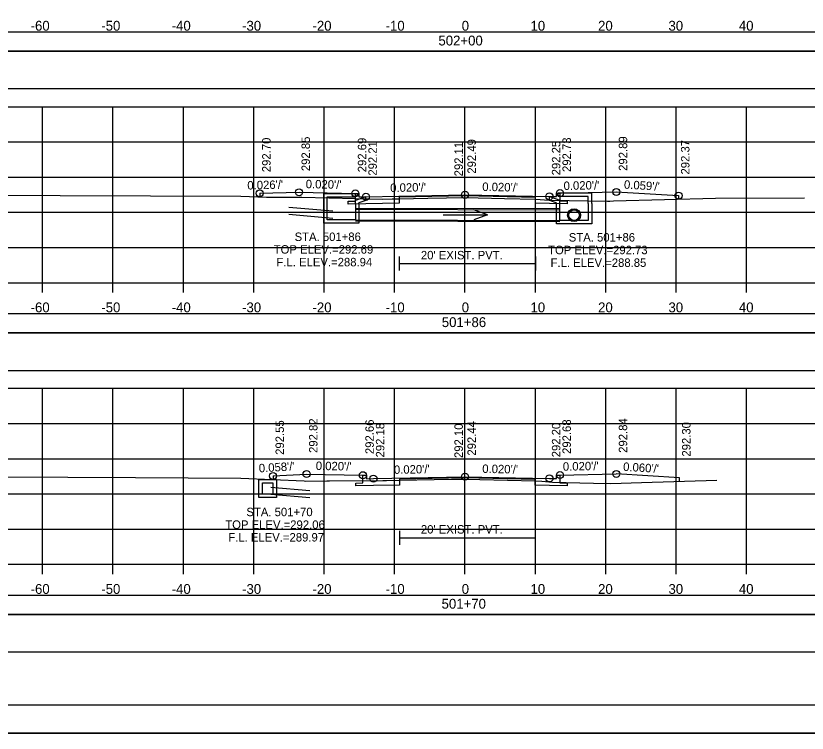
# Model space of a CAD drawing. Extents: x 1370538 to 1372872, y 376220 to 381127.
# Drawn here: x 1372644.8 to 1372757.3, y 376647.1 to 376749 of the extents above; entities that cross this region are included whole.
import ezdxf

# ---------------------------------------------------------------- set-up
doc = ezdxf.new("R2010")
doc.units = 0
for name, color, linetype in [('R_Border', 7, 'Continuous'), ('R_Border Notes', 7, 'Continuous'), ('R_Border PE', 7, 'Continuous'), ('R_Border Prem', 7, 'Continuous'), ('R_Dimension', 7, 'Continuous'), ('R_Fin Surface', 7, 'Continuous'), ('R_Grid', 7, 'Continuous'), ('R_No Plot', 7, 'Continuous'), ('R_Water', 7, 'Continuous'), ('R_Water Annot', 7, 'Continuous'), ('R_Xsect Elev', 7, 'Continuous'), ('R_Xsect Slope', 7, 'Continuous'), ('T_Detection Zones', 7, 'Continuous')]:
    doc.layers.add(name, color=color, linetype=linetype)

msp = doc.modelspace()

# ---------------------------------------------------------------- linework, layer by layer
at = {"layer": 'R_Border'}
for p, q in [((1372699.29, 376714.81), (1372699.29, 376712.81)), ((1372699.29, 376713.81), (1372718.69, 376713.81)), ((1372718.69, 376714.81), (1372718.69, 376712.81)), ((1372699.34, 376675.86), (1372699.34, 376673.86)), ((1372718.62, 376675.86), (1372718.62, 376673.86)), ((1372699.34, 376674.86), (1372718.62, 376674.86))]:
    msp.add_line(p, q, dxfattribs=at)
for points in [[(1372722.15, 376723.82), (1372722.15, 376722.73), (1372723.15, 376722.71), (1372723.15, 376722.29), (1372720.65, 376722.34), (1372718.69, 376722.38), (1372718.69, 376723.21), (1372708.65, 376723.41), (1372699.29, 376723.22), (1372699.29, 376722.39), (1372694.58, 376722.3), (1372692.08, 376722.25), (1372692.08, 376722.66), (1372693.08, 376722.68), (1372693.08, 376723.78)], [(1372722.15, 376683.77), (1372722.15, 376682.68), (1372723.15, 376682.66), (1372723.15, 376682.24), (1372720.65, 376682.29), (1372718.63, 376682.33), (1372718.62, 376683.16), (1372708.65, 376683.36), (1372699.34, 376683.18), (1372699.34, 376682.34), (1372695.65, 376682.27), (1372693.15, 376682.22), (1372693.15, 376682.64), (1372694.15, 376682.66), (1372694.15, 376683.75)]]:
    msp.add_lwpolyline(points, dxfattribs=at)
at = {"layer": 'R_Border Notes'}
msp.add_line((1372866.83, 376651.09), (1372550.65, 376651.09), dxfattribs=at)
at = {"layer": 'R_Border Prem'}
for p, q in [((1372558.65, 376711.09), (1372858.65, 376711.09)), ((1372648.65, 376709.69), (1372648.65, 376711.09)), ((1372658.65, 376709.69), (1372658.65, 376711.09)), ((1372668.65, 376709.69), (1372668.65, 376711.09)), ((1372678.65, 376709.69), (1372678.65, 376711.09)), ((1372688.65, 376709.69), (1372688.65, 376711.09)), ((1372698.65, 376709.69), (1372698.65, 376711.09)), ((1372708.65, 376709.69), (1372708.65, 376711.09)), ((1372718.65, 376709.69), (1372718.65, 376711.09)), ((1372728.65, 376709.69), (1372728.65, 376711.09)), ((1372738.65, 376709.69), (1372738.65, 376711.09)), ((1372748.65, 376709.69), (1372748.65, 376711.09)), ((1372558.65, 376671.09), (1372858.65, 376671.09)), ((1372648.65, 376669.69), (1372648.65, 376671.09)), ((1372658.65, 376669.69), (1372658.65, 376671.09)), ((1372668.65, 376669.69), (1372668.65, 376671.09)), ((1372678.65, 376669.69), (1372678.65, 376671.09)), ((1372688.65, 376669.69), (1372688.65, 376671.09)), ((1372698.65, 376669.69), (1372698.65, 376671.09)), ((1372708.65, 376669.69), (1372708.65, 376671.09)), ((1372718.65, 376669.69), (1372718.65, 376671.09)), ((1372728.65, 376669.69), (1372728.65, 376671.09)), ((1372738.65, 376669.69), (1372738.65, 376671.09)), ((1372748.65, 376669.69), (1372748.65, 376671.09))]:
    msp.add_line(p, q, dxfattribs=at)
at = {"layer": 'R_Dimension'}
for points in [[(1372586.95, 376723.74), (1372676.82, 376723.4), (1372680.47, 376723.25), (1372681.64, 376723.25), (1372685.5, 376723.24), (1372697, 376722.95), (1372698.31, 376722.99), (1372699.29, 376723.02), (1372703.39, 376723.11), (1372708.67, 376723.2), (1372714.27, 376723.07), (1372718.69, 376722.97), (1372720.61, 376722.81), (1372720.74, 376722.8), (1372728.92, 376722.69), (1372729.21, 376722.68), (1372729.74, 376722.7), (1372744.25, 376723.11), (1372756.89, 376723.13)], [(1372558.65, 376683.74), (1372562.8, 376683.64), (1372568.21, 376683.67), (1372584.9, 376683.81), (1372661.87, 376683.41), (1372676.81, 376683.33), (1372685.83, 376682.93), (1372686.06, 376682.92), (1372689.02, 376682.96), (1372689.17, 376682.96), (1372689.39, 376682.96), (1372697, 376682.98), (1372697.51, 376682.99), (1372699.34, 376683.05), (1372706.72, 376683.17), (1372708.67, 376683.19), (1372710.75, 376683.14), (1372718.62, 376682.96), (1372719.59, 376682.88), (1372721.07, 376682.75), (1372726.93, 376682.63), (1372729.37, 376682.58), (1372733.74, 376682.72), (1372744.41, 376683.06)]]:
    msp.add_lwpolyline(points, dxfattribs=at)
at = {"layer": 'R_Fin Surface'}
for p, q in [((1372679.49, 376723.79), (1372679.49, 376723.29)), ((1372738.99, 376723.46), (1372738.99, 376722.96)), ((1372681.39, 376683.64), (1372681.39, 376683.13))]:
    msp.add_line(p, q, dxfattribs=at)
for points in [[(1372679.49, 376723.79), (1372685.08, 376723.94), (1372693.08, 376723.78), (1372693.58, 376723.78), (1372693.58, 376723.28), (1372694.58, 376723.3), (1372708.65, 376723.58), (1372720.65, 376723.34), (1372721.65, 376723.32), (1372721.65, 376723.82), (1372722.15, 376723.82), (1372730.15, 376723.98), (1372738.99, 376723.46)], [(1372681.39, 376683.64), (1372686.15, 376683.91), (1372694.15, 376683.75), (1372694.65, 376683.75), (1372694.65, 376683.25), (1372695.65, 376683.27), (1372708.65, 376683.53), (1372720.65, 376683.29), (1372721.65, 376683.27), (1372721.65, 376683.77), (1372722.15, 376683.77), (1372730.15, 376683.93)], [(1372739.14, 376682.89), (1372739.14, 376683.39), (1372730.15, 376683.93)]]:
    msp.add_lwpolyline(points, dxfattribs=at)
at = {"layer": 'R_Grid'}
for p, q in [((1372558.65, 376736.09), (1372858.65, 376736.09)), ((1372648.65, 376711.09), (1372648.65, 376736.09)), ((1372658.65, 376711.09), (1372658.65, 376736.09)), ((1372668.65, 376711.09), (1372668.65, 376736.09)), ((1372678.65, 376711.09), (1372678.65, 376736.09)), ((1372688.65, 376711.09), (1372688.65, 376736.09)), ((1372698.65, 376711.09), (1372698.65, 376736.09)), ((1372708.65, 376711.09), (1372708.65, 376736.09)), ((1372718.65, 376711.09), (1372718.65, 376736.09)), ((1372728.65, 376711.09), (1372728.65, 376736.09)), ((1372738.65, 376711.09), (1372738.65, 376736.09)), ((1372748.65, 376711.09), (1372748.65, 376736.09)), ((1372558.65, 376731.09), (1372858.65, 376731.09)), ((1372558.65, 376726.09), (1372858.65, 376726.09)), ((1372558.65, 376721.09), (1372858.65, 376721.09)), ((1372558.65, 376716.09), (1372858.65, 376716.09)), ((1372558.65, 376711.09), (1372858.65, 376711.09)), ((1372558.65, 376696.09), (1372858.65, 376696.09)), ((1372648.65, 376671.09), (1372648.65, 376696.09)), ((1372658.65, 376671.09), (1372658.65, 376696.09)), ((1372668.65, 376671.09), (1372668.65, 376696.09)), ((1372678.65, 376671.09), (1372678.65, 376696.09)), ((1372688.65, 376671.09), (1372688.65, 376696.09)), ((1372698.65, 376671.09), (1372698.65, 376696.09)), ((1372708.65, 376671.09), (1372708.65, 376696.09)), ((1372718.65, 376671.09), (1372718.65, 376696.09)), ((1372728.65, 376671.09), (1372728.65, 376696.09)), ((1372738.65, 376671.09), (1372738.65, 376696.09)), ((1372748.65, 376671.09), (1372748.65, 376696.09)), ((1372558.65, 376691.09), (1372858.65, 376691.09)), ((1372558.65, 376686.09), (1372858.65, 376686.09)), ((1372558.65, 376681.09), (1372858.65, 376681.09)), ((1372558.65, 376676.09), (1372858.65, 376676.09)), ((1372558.65, 376671.09), (1372858.65, 376671.09))]:
    msp.add_line(p, q, dxfattribs=at)
at = {"layer": 'R_No Plot'}
for p, q in [((1372683.61, 376721.84), (1372689.88, 376721.29)), ((1372693.08, 376721.7), (1372722.15, 376721.61)), ((1372683.61, 376720.83), (1372689.88, 376720.27)), ((1372693.08, 376719.86), (1372722.15, 376719.78)), ((1372681.07, 376682.07), (1372686.59, 376681.58)), ((1372681.07, 376681.05), (1372686.59, 376680.57)), ((1372538.25, 376647.11), (1372871.58, 376647.11))]:
    msp.add_line(p, q, dxfattribs=at)
for points in [[(1372538.24, 376860.44), (1372871.58, 376860.44), (1372871.58, 376647.11), (1372538.24, 376647.11)], [(1372784.57, 376856.55), (1372784.57, 376846.67), (1372820.3, 376846.67), (1372820.3, 376843.75), (1372843.5, 376843.75), (1372843.5, 376819.42), (1372866.83, 376819.42), (1372866.83, 376651.09), (1372550.65, 376651.09), (1372550.65, 376856.55)]]:
    msp.add_lwpolyline(points, close=True, dxfattribs=at)
for centre, radius in [((1372679.49, 376723.79), 0.5), ((1372685.08, 376723.94), 0.5), ((1372693.08, 376723.78), 0.5), ((1372708.65, 376723.58), 0.5), ((1372722.15, 376723.82), 0.5), ((1372730.15, 376723.98), 0.5), ((1372738.99, 376723.46), 0.5), ((1372694.58, 376723.3), 0.5), ((1372720.65, 376723.34), 0.5), ((1372724.15, 376720.69), 0.917), ((1372681.39, 376683.64), 0.5), ((1372686.15, 376683.91), 0.5), ((1372694.15, 376683.75), 0.5), ((1372695.65, 376683.27), 0.5), ((1372708.65, 376683.53), 0.5), ((1372720.65, 376683.29), 0.5), ((1372722.15, 376683.77), 0.5), ((1372730.15, 376683.93), 0.5)]:
    msp.add_circle(centre, radius, dxfattribs=at)
at = {"layer": 'R_Water'}
for p, q in [((1372688.58, 376723.78), (1372693.33, 376723.78)), ((1372688.58, 376722.28), (1372688.58, 376723.78)), ((1372689.08, 376722.28), (1372689.08, 376723.28)), ((1372689.08, 376723.28), (1372693.08, 376723.28)), ((1372693.41, 376723.61), (1372693.08, 376723.28)), ((1372694.58, 376723.3), (1372693.08, 376722.78)), ((1372693.41, 376723.61), (1372693.33, 376723.78)), ((1372720.65, 376723.34), (1372722.15, 376722.82)), ((1372720.65, 376722.81), (1372721.65, 376722.46)), ((1372721.81, 376723.65), (1372721.9, 376723.82)), ((1372721.81, 376723.65), (1372722.15, 376723.32)), ((1372726.65, 376723.82), (1372721.9, 376723.82)), ((1372726.15, 376723.32), (1372722.15, 376723.32)), ((1372722.15, 376722.32), (1372722.15, 376722.82)), ((1372726.15, 376722.32), (1372726.15, 376723.32)), ((1372726.65, 376722.32), (1372726.65, 376723.82)), ((1372683.61, 376721.84), (1372689.88, 376721.28)), ((1372693.08, 376722.28), (1372693.08, 376722.78)), ((1372694.58, 376722.77), (1372693.58, 376722.42)), ((1372693.58, 376722.28), (1372693.58, 376722.42)), ((1372721.65, 376722.32), (1372721.65, 376722.46)), ((1372683.61, 376720.84), (1372689.88, 376720.28)), ((1372693.08, 376721.53), (1372722.15, 376721.44)), ((1372693.08, 376720.03), (1372722.15, 376719.94)), ((1372681.07, 376682.06), (1372686.59, 376681.57)), ((1372681.07, 376681.06), (1372686.59, 376680.57))]:
    msp.add_line(p, q, dxfattribs=at)
for points in [[(1372694.58, 376722.77), (1372694.58, 376723.3)], [(1372720.65, 376722.81), (1372720.65, 376723.34)], [(1372693.58, 376722.28), (1372693.58, 376719.53), (1372691.08, 376719.53), (1372688.58, 376719.53), (1372688.58, 376722.28)], [(1372693.08, 376722.28), (1372693.08, 376720.03), (1372691.08, 376720.03), (1372689.08, 376720.03), (1372689.08, 376722.28)], [(1372726.65, 376722.32), (1372726.65, 376719.44), (1372724.15, 376719.44), (1372721.65, 376719.44), (1372721.65, 376722.32)], [(1372726.15, 376722.32), (1372726.15, 376719.94), (1372724.15, 376719.94), (1372722.15, 376719.94), (1372722.15, 376722.32)]]:
    msp.add_lwpolyline(points, dxfattribs=at)
for points in [[(1372680.62, 376683.15), (1372681.87, 376683.15), (1372681.87, 376680.56), (1372680.62, 376680.56), (1372679.37, 376680.56), (1372679.37, 376683.15)], [(1372680.62, 376682.65), (1372681.37, 376682.65), (1372681.37, 376681.06), (1372680.62, 376681.06), (1372679.87, 376681.06), (1372679.87, 376682.65)]]:
    msp.add_lwpolyline(points, close=True, dxfattribs=at)
msp.add_circle((1372724.15, 376720.69), 0.75, dxfattribs=at)
at = {"layer": 'R_Water Annot'}
for p, q in [((1372705.55, 376720.75), (1372711.83, 376720.73)), ((1372711.83, 376720.73), (1372709.91, 376721.43)), ((1372711.83, 376720.73), (1372709.91, 376720.03))]:
    msp.add_line(p, q, dxfattribs=at)
at = {"layer": 'R_Xsect Elev'}
for p, q in [((1372708.65, 376723.2), (1372708.65, 376733.2)), ((1372708.65, 376683.19), (1372708.65, 376693.19))]:
    msp.add_line(p, q, dxfattribs=at)
at = {"layer": 'T_Detection Zones'}
for points in [[(1372552.66, 376743.99), (1372864.63, 376743.99), (1372864.63, 376746.69), (1372552.66, 376746.69)], [(1372552.66, 376738.66), (1372864.63, 376738.66), (1372864.63, 376743.99), (1372552.66, 376743.99)], [(1372552.66, 376703.96), (1372864.63, 376703.96), (1372864.63, 376706.67), (1372552.66, 376706.67)], [(1372552.66, 376698.64), (1372864.63, 376698.64), (1372864.63, 376703.96), (1372552.66, 376703.96)], [(1372552.66, 376663.98), (1372864.63, 376663.98), (1372864.63, 376666.68), (1372552.66, 376666.68)], [(1372552.66, 376658.66), (1372864.63, 376658.66), (1372864.63, 376663.98), (1372552.66, 376663.98)]]:
    msp.add_lwpolyline(points, close=True, dxfattribs=at)

# ---------------------------------------------------------------- texts
at = {"layer": 'R_Border PE'}
for s, p in [('-60', (1372646.95, 376746.89)), ('-50', (1372656.99, 376746.89)), ('-40', (1372666.99, 376746.89)), ('-30', (1372676.99, 376746.89)), ('-20', (1372686.99, 376746.89)), ('-10', (1372697.38, 376746.89)), ('0', (1372708.19, 376746.89)), ('10', (1372717.96, 376746.89)), ('20', (1372727.56, 376746.89)), ('30', (1372737.56, 376746.89)), ('40', (1372747.56, 376746.89)), ('502+00', (1372704.88, 376744.79)), ('-60', (1372646.95, 376706.89)), ('-50', (1372656.99, 376706.89)), ('-40', (1372666.99, 376706.89)), ('-30', (1372676.99, 376706.89)), ('-20', (1372686.99, 376706.89)), ('-10', (1372697.38, 376706.89)), ('0', (1372708.19, 376706.89)), ('10', (1372717.96, 376706.89)), ('20', (1372727.56, 376706.89)), ('30', (1372737.56, 376706.89)), ('40', (1372747.56, 376706.89)), ('501+86', (1372705.36, 376704.79)), ('-60', (1372646.95, 376666.89)), ('-50', (1372656.99, 376666.89)), ('-40', (1372666.99, 376666.89)), ('-30', (1372676.99, 376666.89)), ('-20', (1372686.99, 376666.89)), ('-10', (1372697.38, 376666.89)), ('0', (1372708.19, 376666.89)), ('10', (1372717.96, 376666.89)), ('20', (1372727.56, 376666.89)), ('30', (1372737.56, 376666.89)), ('40', (1372747.56, 376666.89)), ('501+70', (1372705.33, 376664.79))]:
    msp.add_text(s, height=1.4, dxfattribs=at).set_placement(p)
at = {"layer": 'R_Water'}
for p in [(1372702.39, 376714.41), (1372702.39, 376675.46)]:
    msp.add_text("20' EXIST. PVT.", height=1.2, dxfattribs=at).set_placement(p)
at = {"layer": 'R_Water Annot'}
for s, p in [('STA. 501+86', (1372684.45, 376717.02)), ('STA. 501+86', (1372723.4, 376716.94)), ('TOP ELEV.=292.69', (1372681.48, 376715.22)), ('TOP ELEV.=292.73', (1372720.46, 376715.14)), ('F.L. ELEV.=288.94', (1372681.87, 376713.42)), ('F.L. ELEV.=288.85', (1372720.81, 376713.34)), ('STA. 501+70', (1372677.6, 376677.93)), ('TOP ELEV.=292.06', (1372674.6, 376676.13)), ('F.L. ELEV.=289.97', (1372675.03, 376674.33))]:
    msp.add_text(s, height=1.2, dxfattribs=at).set_placement(p)
at = {"layer": 'R_Xsect Elev'}
for s, rotation, p in [('292.85', 90, (1372686.63, 376726.94)), ('292.89', 90, (1372731.7, 376726.98)), ('292.70', 90, (1372681.04, 376726.79)), ('292.69', 90, (1372694.63, 376726.78)), ('292.21', 90, (1372696.13, 376726.3)), ('292.11', 90, (1372708.35, 376726.2)), ('292.49', 90, (1372710.2, 376726.58)), ('292.25', 90, (1372722.2, 376726.34)), ('292.73', 90, (1372723.7, 376726.82)), ('292.37', 90, (1372740.54, 376726.46)), ("0.059'/'", 356.6454, (1372731.21, 376724.46)), ('292.55', 90, (1372682.94, 376686.64)), ('292.82', 90, (1372687.7, 376686.91)), ('292.66', 90, (1372695.7, 376686.75)), ('292.44', 90, (1372710.2, 376686.53)), ('292.68', 90, (1372723.7, 376686.77)), ('292.84', 90, (1372731.7, 376686.93)), ('292.18', 90, (1372697.2, 376686.27)), ('292.10', 90, (1372708.35, 376686.19)), ('292.20', 90, (1372722.2, 376686.29)), ('292.30', 90, (1372740.69, 376686.39)), ("0.060'/'", 356.5817, (1372731.09, 376684.38))]:
    msp.add_text(s, height=1.2, rotation=rotation, dxfattribs=at).set_placement(p)
at = {"layer": 'R_Xsect Slope'}
for s, rotation, p in [("0.026'/'", 1.4964, (1372677.75, 376724.32)), ("0.020'/'", 358.8542, (1372686.02, 376724.52)), ("0.020'/'", 1.1458, (1372698.04, 376723.97)), ("0.020'/'", 358.8542, (1372711.1, 376724.13)), ("0.020'/'", 1.1458, (1372722.67, 376724.26)), ("0.020'/'", 358.8542, (1372687.45, 376684.5)), ("0.020'/'", 1.1458, (1372722.57, 376684.38)), ("0.058'/'", 3.3178, (1372679.4, 376684.14)), ("0.020'/'", 1.1458, (1372698.57, 376683.93)), ("0.020'/'", 358.8542, (1372711.1, 376684.08))]:
    msp.add_text(s, height=1.2, rotation=rotation, dxfattribs=at).set_placement(p)

doc.saveas('drawing.dxf')
